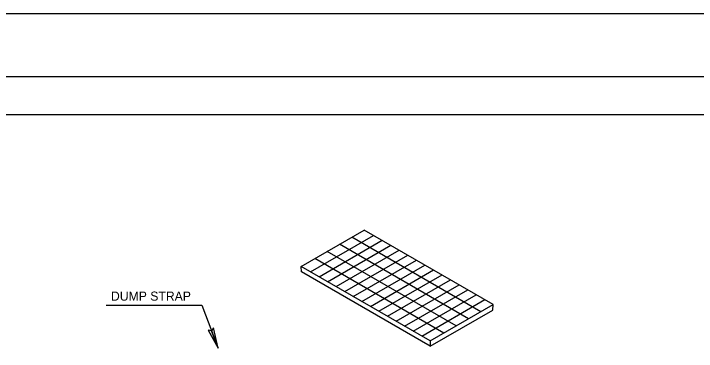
# Model space of a CAD drawing. Extents: x -120.7 to -50.3, y -20.2 to 3.8.
# Drawn here: x -80.79 to -71.81, y -0.68 to 3.76 of the extents above; entities that cross this region are included whole.
import ezdxf

# ---------------------------------------------------------------- set-up
doc = ezdxf.new("R2010")
doc.units = 0
for name, color, linetype in [('Default', 7, 'Continuous'), ('PR_Dimensions', 7, 'Continuous'), ('SHT_Plot_Shape_Full', 7, 'Continuous'), ('SHT_Plot_Shape_Half', 7, 'Continuous'), ('SHT_Sheet_Border', 7, 'Continuous'), ('TYP_Typical_Section_Linework', 7, 'Continuous'), ('TYP_Typical_Section_Txt', 7, 'Continuous')]:
    doc.layers.add(name, color=color, linetype=linetype)

# ---------------------------------------------------------------- blocks, each defined once
blk = doc.blocks.new('AR32_1')
at = {"layer": 'Default'}
for p, q in [((0, 0), (-11.43, 1.6)), ((-11.43, 1.6), (-10.39, -0.01)), ((-11.42, -1.63), (0, 0)), ((-10.39, -0.01), (-11.42, -1.63))]:
    blk.add_line(p, q, dxfattribs=at)

msp = doc.modelspace()

# ---------------------------------------------------------------- linework, layer by layer
at = {"layer": 'PR_Dimensions'}
for p, q in [((-79.5769, -0.0732), (-78.3194, -0.0732)), ((-78.3194, -0.0732), (-78.1036, -0.6397)), ((-78.2356, -0.4013), (-78.1036, -0.6397)), ((-78.1913, -0.4105), (-78.2356, -0.4013)), ((-78.1645, -0.374), (-78.1911, -0.4101)), ((-78.1036, -0.6397), (-78.191, -0.4103)), ((-78.1036, -0.6397), (-78.1645, -0.374))]:
    msp.add_line(p, q, dxfattribs=at)
for points in [[(-78.191, -0.4103), (-78.1913, -0.4105)], [(-78.1911, -0.4101), (-78.191, -0.4103), (-78.1036, -0.6397)]]:
    msp.add_lwpolyline(points, dxfattribs=at)
at = {"layer": 'SHT_Plot_Shape_Full'}
msp.add_lwpolyline([(-86.2592, 3.7586), (-50.2592, 3.7586), (-50.2592, -20.2414), (-86.2592, -20.2414)], close=True, dxfattribs=at)
at = {"layer": 'SHT_Plot_Shape_Half'}
msp.add_lwpolyline([(-84.6217, 2.9337), (-50.6217, 2.9337), (-50.6217, -19.0663), (-84.6217, -19.0663)], close=True, dxfattribs=at)
at = {"layer": 'SHT_Sheet_Border'}
msp.add_lwpolyline([(-51.1717, -18.5663), (-82.6717, -18.5663), (-82.6717, 2.4337), (-51.1717, 2.4337)], close=True, dxfattribs=at)
at = {"layer": 'TYP_Typical_Section_Linework'}
for p, q in [((-77.0096, 0.4345), (-76.1803, 0.9133)), ((-74.4832, -0.0665), (-76.1803, 0.9133)), ((-76.8876, 0.364), (-76.0582, 0.8429)), ((-74.6457, -0.1603), (-76.3428, 0.8195)), ((-76.7751, 0.2991), (-75.9457, 0.7779)), ((-74.8082, -0.2541), (-76.5053, 0.7257)), ((-74.9707, -0.3479), (-76.6678, 0.6319)), ((-76.6626, 0.2341), (-75.8332, 0.713)), ((-76.5501, 0.1692), (-75.7207, 0.648)), ((-76.4376, 0.1042), (-75.6082, 0.5831)), ((-75.1332, -0.4417), (-76.8303, 0.5381)), ((-76.3251, 0.0393), (-75.4957, 0.5181)), ((-76.2126, -0.0257), (-75.3832, 0.4531)), ((-75.3126, -0.5453), (-77.0096, 0.4345)), ((-77.005, 0.3625), (-77.0096, 0.4345)), ((-75.3126, -0.6146), (-77.005, 0.3625)), ((-76.1001, -0.0907), (-75.2707, 0.3882)), ((-75.9876, -0.1556), (-75.1582, 0.3232)), ((-75.8751, -0.2206), (-75.0457, 0.2583)), ((-75.7626, -0.2855), (-74.9332, 0.1933)), ((-75.6501, -0.3505), (-74.8207, 0.1284)), ((-75.5376, -0.4154), (-74.7082, 0.0634)), ((-75.4251, -0.4804), (-74.5957, -0.0015)), ((-75.3126, -0.5453), (-74.4832, -0.0665)), ((-74.4878, -0.1384), (-74.4832, -0.0665)), ((-75.3126, -0.6146), (-74.4878, -0.1384)), ((-75.3126, -0.5453), (-75.3126, -0.6146))]:
    msp.add_line(p, q, dxfattribs=at)

# ---------------------------------------------------------------- block references
at = {"layer": 'PR_Dimensions', "xscale": 0.02362196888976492, "yscale": 0.023621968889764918, "rotation": -69.15520631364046}
msp.add_blockref('AR32_1', (-78.1036, -0.6397), dxfattribs=at)

# ---------------------------------------------------------------- texts
at = {"layer": 'TYP_Typical_Section_Txt'}
msp.add_text('DUMP STRAP', height=0.12, dxfattribs=at).set_placement((-79.5134, -0.0158))

doc.saveas('drawing.dxf')
